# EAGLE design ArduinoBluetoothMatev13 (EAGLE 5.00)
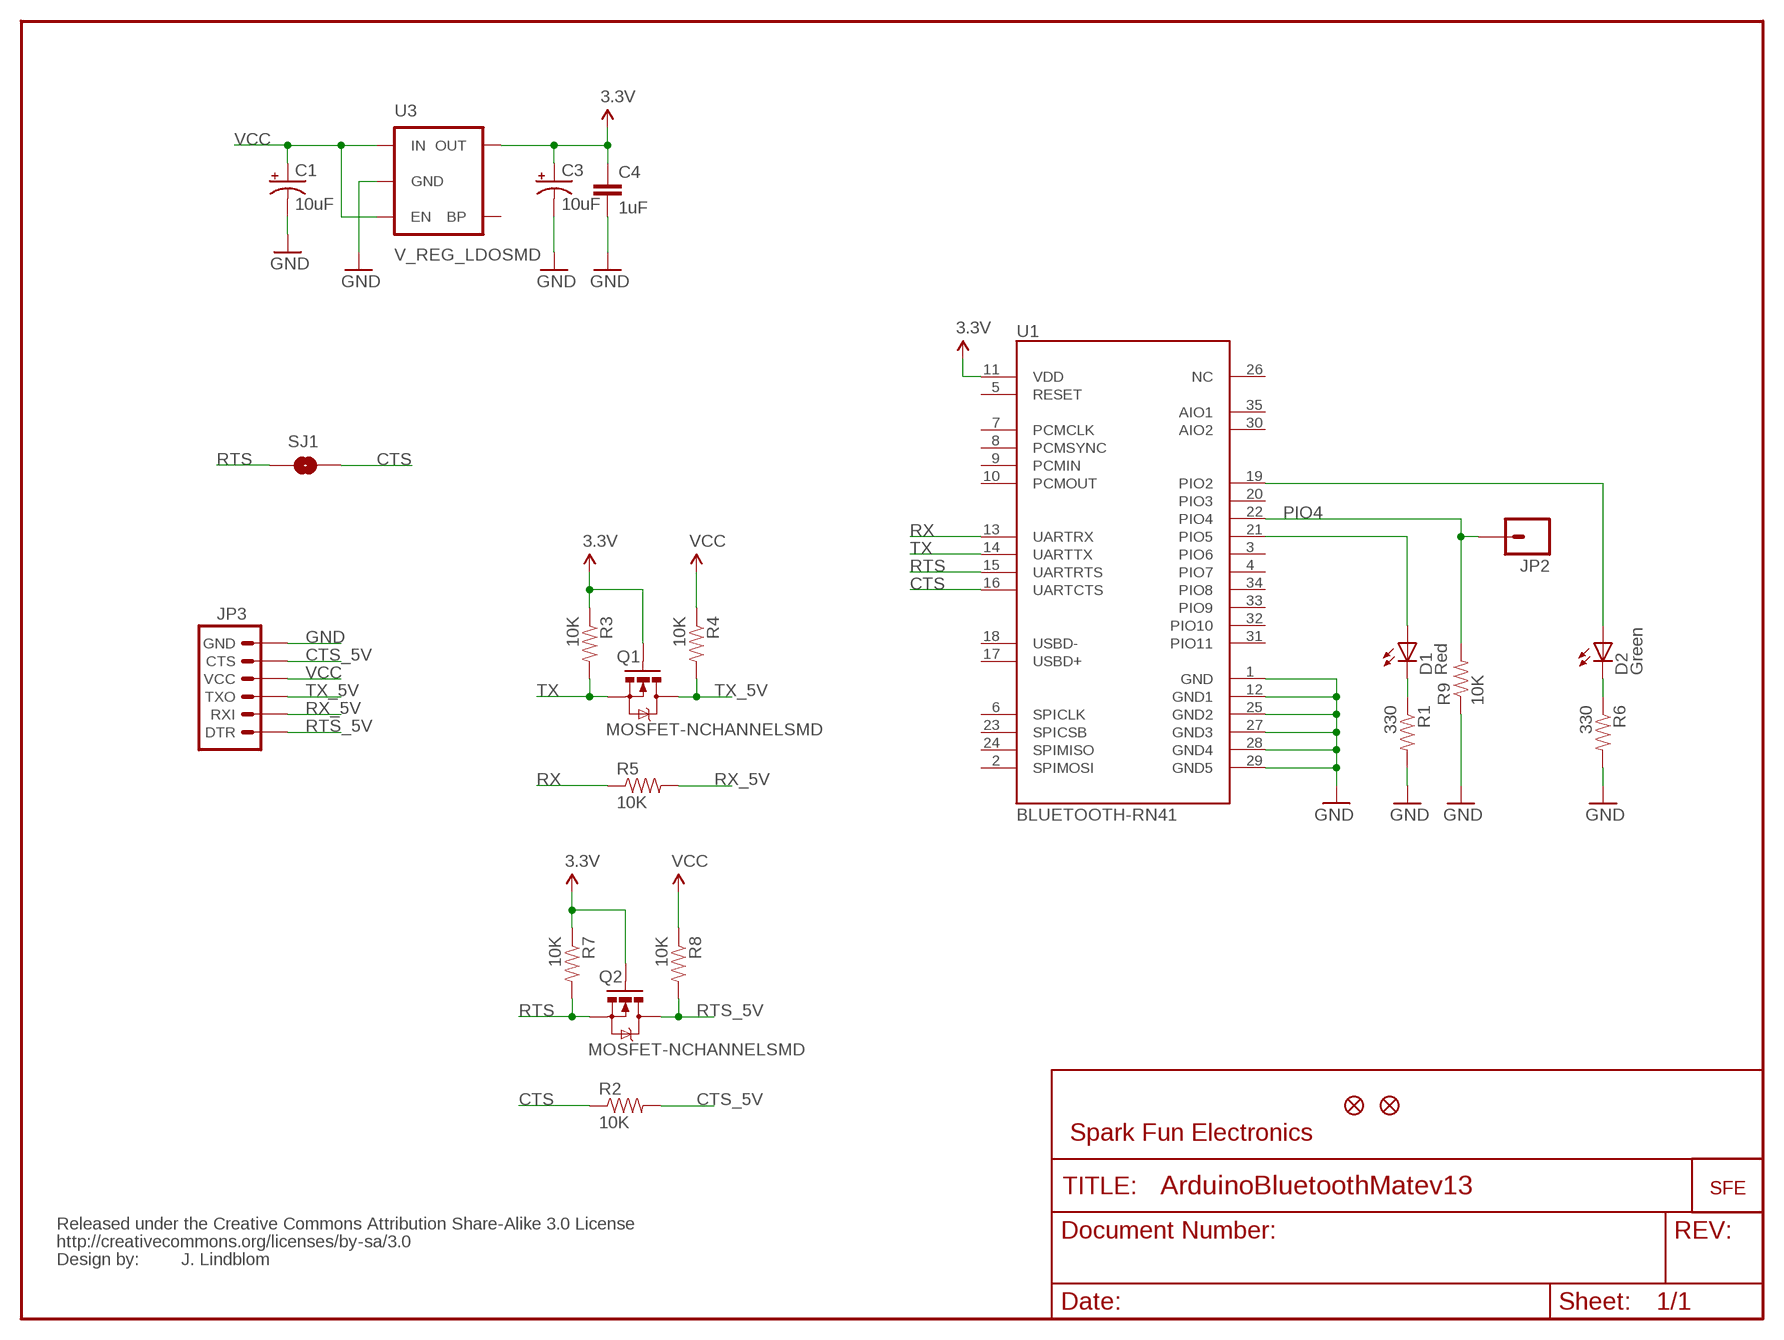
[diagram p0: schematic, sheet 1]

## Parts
C1  10uF  CAP_POL1206  [EIA3216]
C3  10uF  CAP_POL1206  [EIA3216]
C4  1uF  CAP0402-CAP  [0402-CAP]
D1  Red  LED0603  [LED-0603]
D2  Green  LED0603  [LED-0603]
JP1  FIDUCIAL1X2  [FIDUCIAL-1X2]
JP2  M01SMDNS  [1X01NS]
JP3  ARDUINO_SERIAL_PROGRAMPTH  [1X06]
JP4  FIDUCIAL1X2  [FIDUCIAL-1X2]
Q1  MOSFET-NCHANNELSMD  [SOT23-3]
Q2  MOSFET-NCHANNELSMD  [SOT23-3]
R1  330  RESISTOR0402-RES  [0402-RES]
R2  10K  RESISTOR0402-RES  [0402-RES]
R3  10K  RESISTOR0402-RES  [0402-RES]
R4  10K  RESISTOR0402-RES  [0402-RES]
R5  10K  RESISTOR0402-RES  [0402-RES]
R6  330  RESISTOR0402-RES  [0402-RES]
R7  10K  RESISTOR0402-RES  [0402-RES]
R8  10K  RESISTOR0402-RES  [0402-RES]
R9  10K  RESISTOR0402-RES  [0402-RES]
SJ1  SOLDERJUMPERNO  [SJ_2S-NO]
U1  BLUETOOTH-RN41  BLUETOOTH-RN41"  [RN41]
U3  V_REG_LDOSMD  [SOT23-5]
U$1  LOGO-SFENEW  [SFE-NEW-WEBLOGO]
U$2  CREATIVE_COMMONS  [CREATIVE_COMMONS]

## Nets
3.3V: C3.A(+) C4.1 Q1.1(G) Q2.1(G) R3.1 R7.1 U1.11(VDD) U3.5(OUT)
CTS: R2.1 SJ1.2 U1.16(UARTCTS)
CTS_5V: JP3.5(CTS) R2.2
D1: D1.C R1.1
D2: D2.C R6.1
GND: C1.C(-) C3.C(-) C4.2 JP3.6(GND) R1.2 R6.2 R9.1 U1.1(GND) U1.12(GND1) U1.25(GND2) U1.27(GND3) U1.28(GND4) U1.29(GND5) U3.2(GND)
N$1: D1.A U1.21(PIO5)
N$2: D2.A U1.19(PIO2)
PIO4: JP2.1 R9.2 U1.22(PIO4)
RTS: Q2.2(S) R7.2 SJ1.1 U1.15(UARTRTS)
RTS_5V: JP3.1(DTR) Q2.3(D) R8.2
RX: R5.1 U1.13(UARTRX)
RX_5V: JP3.2(RXI) R5.2
TX: Q1.2(S) R3.2 U1.14(UARTTX)
TX_5V: JP3.3(TXO) Q1.3(D) R4.2
VCC: C1.A(+) JP3.4(VCC) R4.1 R8.1 U3.1(IN) U3.3(EN)
Unconnected: U1.2(SPIMOSI) U1.3(PIO6) U1.4(PIO7) U1.5(RESET) U1.6(SPICLK) U1.7(PCMCLK) U1.8(PCMSYNC) U1.9(PCMIN) U1.10(PCMOUT) U1.17(USBD+) U1.18(USBD-) U1.20(PIO3) U1.23(SPICSB) U1.24(SPIMISO) U1.26(NC) U1.30(AIO2) U1.31(PIO11) U1.32(PIO10) U1.33(PIO9) U1.34(PIO8) U1.35(AIO1) U3.4(BP)

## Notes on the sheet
- Spark Fun Electronics
- J. Lindblom

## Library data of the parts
C1 C3 = SparkFun:CAP_POL: Capacitor Polarized
C4 = SparkFun:CAP: Capacitor
D1 D2 = SparkFun:LED: LEDs
JP1 JP4 = SparkFun:FIDUCIAL: Fiducial Alignment Points
JP2 = SparkFun:M01: Header 1
JP3 = SparkFun:ARDUINO_SERIAL_PROGRAM
Q1 Q2 = SparkFun:MOSFET-NCHANNEL
R1-R9 = SparkFun:RESISTOR: Resistor
SJ1 = SparkFun:SOLDERJUMPER: Solder Jumper
U1 = ScratchPad:BLUETOOTH-RN41
U3 = SparkFun:V_REG_LDO: Voltage Regulator LDO Standard 150mA LDO voltage regulator in SOT-23 layout. Micrel part MIC5205. BP (by-pass) pin is used to lower output noise with 470pF cap.
U$1 = SparkFun:LOGO-SFE: Spark Fun Electronics PCB Logo
U$2 = SparkFun:CREATIVE_COMMONS

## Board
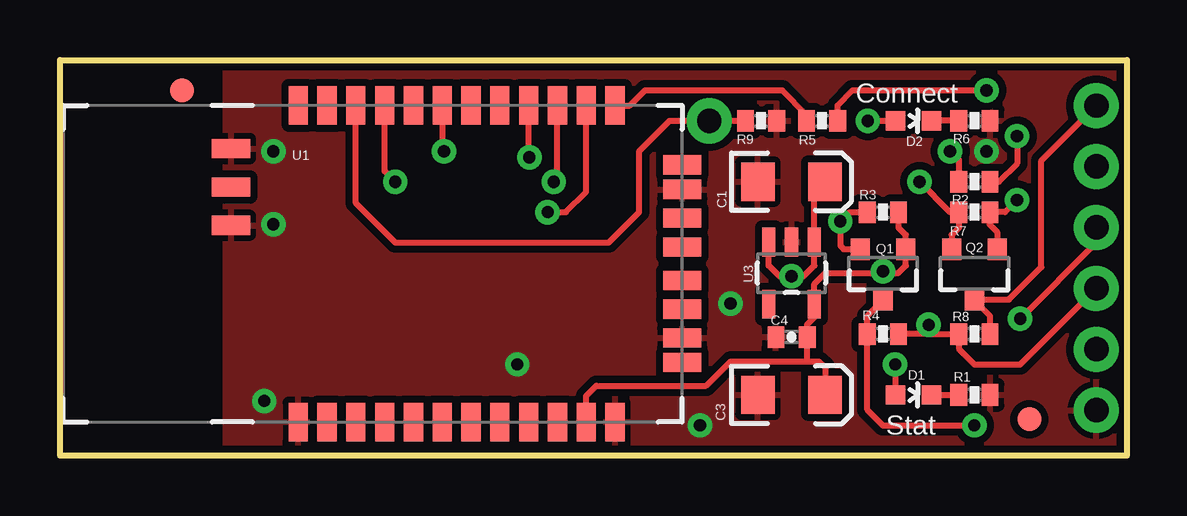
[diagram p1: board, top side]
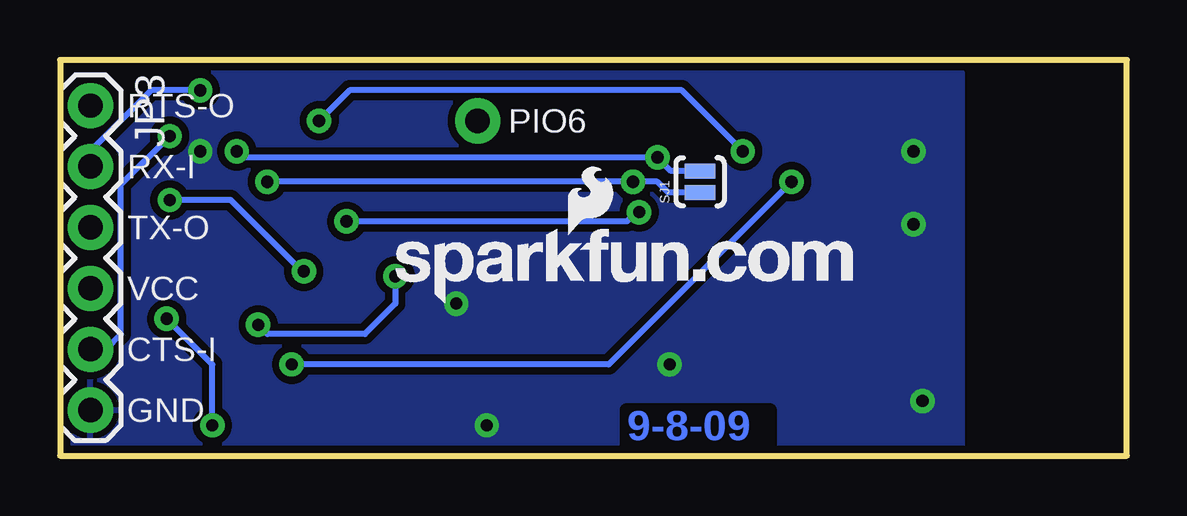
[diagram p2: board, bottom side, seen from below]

Size 44.45 x 16.51 mm. Coordinates in mm from the lower left corner, seen from the top.
Outline: 0,0 0,16.51 44.45,16.51 44.45,0 0,0
Copper layers (1*16): Top 0.035mm / dielectric 1.5mm / Bottom 0.035mm
Design rules "SparkFun": minimum track width 8mil, minimum drill 20mil, track to track 8mil, track to pad 8mil, pad to pad 8mil, via to via 8mil, smd to smd 8mil, copper to edge 9mil, drill to drill 8mil, minimum pad ring 12mil, minimum via ring 10mil, stop-mask expansion 4mil, vias tented up to drill 20mil, thermal gap 10mil

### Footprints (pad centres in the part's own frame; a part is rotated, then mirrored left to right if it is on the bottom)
EIA3216 = smd 1.4 x 1.6: A 1.4,0; C -1.4,0
0402-CAP = smd 0.7 x 0.9: 1 -0.65,0; 2 0.65,0
LED-0603 = smd 0.8 x 0.8: A 0,-0.75; C 0,0.75
FIDUCIAL-1X2 = smd 1 x 1: 1 0,0
1X01NS = drill 1.016 pad 1.88 round: 1 0,0
1X06 = drill 1.016 pad 1.88 round: 1 0,0; 2 2.54,0; 3 5.08,0; 4 7.62,0; 5 10.16,0; 6 12.7,0
SOT23-3 = smd 0.8 x 0.9: 1 -0.95,-1; 2 0.95,-1; 3 0,1.1
0402-RES = smd 0.7 x 0.9: 1 -0.65,0; 2 0.65,0
SJ_2S-NO = smd 0.635 x 1.27: 1 -0.45,0; 2 0.45,0
RN41 = smd 0.8 x 1.6: 1 -6.6,-6.6; 2 -5.4,-6.6; 3 -4.2,-6.6; 4 -3,-6.6; 5 -1.8,-6.6; 6 -0.6,-6.6; 7 0.6,-6.6; 8 1.8,-6.6; 9 3,-6.6; 10 4.2,-6.6; 11 5.4,-6.6; 12 6.6,-6.6; 13 6.6,6.6; 14 5.4,6.6; 15 4.2,6.6; 16 3,6.6; 17 1.8,6.6; 18 0.6,6.6; 19 -0.6,6.6; 20 -1.8,6.6; 21 -3,6.6; 22 -4.2,6.6; 23 -5.4,6.6; 24 -6.6,6.6 | smd 1.6 x 0.8: 25 -9.4,4.8; 26 -9.4,3.2; 27 -9.4,1.6; 28 9.4,3.1; 29 9.4,-3.1; 30 9.4,-4.122; 31 9.4,-1.9; 32 9.4,-0.7; 33 9.4,0.7; 34 9.4,1.9; 35 9.4,4.122
SOT23-5 = smd 0.55 x 1.2: 1 -0.95,-1.3; 2 0,-1.3; 3 0.95,-1.3; 4 0.95,1.3; 5 -0.95,1.3

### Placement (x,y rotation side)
C1  30.48,11.43 0 top
C3  30.48,2.54 0 top
C4  30.48,4.95 180 top
D1  35.56,2.54 270 top
D2  35.56,13.97 270 top
JP1  40.39,1.52 0 top
JP2  27.05,13.97 0 top
JP3  43.18,14.61 270 bottom
JP4  5.08,15.24 0 top
Q1  34.29,7.62 180 top
Q2  38.1,7.62 180 top
R1  38.1,2.54 0 top
R2  38.1,11.43 0 top
R3  34.29,10.16 180 top
R4  34.29,5.08 180 top
R5  31.75,13.97 0 top
R6  38.1,13.97 0 top
R7  38.1,10.16 180 top
R8  38.1,5.08 0 top
R9  29.21,13.97 180 top
SJ1  17.78,11.43 90 bottom
U1  16.53,8.01 0 top
U3  30.48,7.62 180 top
U$1  30.48,6.35 0 bottom
U$2  not placed on the board

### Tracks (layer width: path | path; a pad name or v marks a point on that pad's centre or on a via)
3.3V  (via drill 0.51)
  Top 0.254: Q2.1 39.05,9.34 38.73,9.65 38.75,9.67 R7.1 39.37,10.16 v39.88,10.67 | R3.1 34.94,9.51 35.24,9.21 Q1.1 35.24,7.93 34.92,7.62 34.29,7.62 | C3.A 31.88,3.68 31.62,3.94 31.11,3.94 | U1.11 21.93,2.5 22.35,2.92 26.92,2.92 27.94,3.94 31.11,3.94 | 34.29,7.62 31.88,7.62 31.43,7.17 U3.5 31.43,5.78 31.11,5.46 31.13,5.45 C4.1 31.13,3.95 31.11,3.94 | 34.29,7.62 v34.29,7.7
  Bottom 0.254: v39.88,10.67 37.34,10.67 34.29,7.62 v34.29,7.7
CTS  (via drill 0.51)
  Top 0.254: U1.16 19.53,12.48 v19.56,12.45 | R2.1 37.45,12.33 v37.08,12.7
  Bottom 0.254: SJ1.2 18.99,11.88 v19.56,12.45 36.83,12.45 v37.08,12.7
CTS_5V  (via drill 0.51)
  Top 0.254: R2.2 39.12,11.43 39.88,12.19 v39.88,13.34
  Bottom 0.254: JP3.5 42.55,4.45 41.91,5.08 41.91,11.3 v39.88,13.34
D1
  Top 0.254: 37.47,2.54 R1.1 D1.C
D2
  Top 0.254: 37.47,13.97 R6.1 D2.C
GND  (via drill 0.51)
  other vias: 27.94,6.35 26.67,1.27 38.61,12.7 8.89,12.7 8.89,9.65 8.51,2.29 19.05,3.81
  pour Bottom (isolate 0.305): 6.86,0 44.4,0 44.4,16 6.86,16
  pour Top (isolate 0.305): 6.86,0 44.4,0 44.4,16 6.86,16
N$1  (via drill 0.51)
  Top 0.254: D1.A 34.81,3.29 v34.8,3.81 | U1.21 13.53,11.87 v13.97,11.43
  Bottom 0.254: v34.8,3.81 21.59,3.81 v13.97,11.43
N$2  (via drill 0.51)
  Top 0.254: U1.19 15.93,12.78 v16,12.7 | v33.66,13.97 D2.A
  Bottom 0.254: v16,12.7 18.54,15.24 32.38,15.24 v33.66,13.97
PIO4
  Top 0.254: U1.22 12.33,10.53 13.97,8.89 22.86,8.89 24.13,10.16 24.13,12.7 25.4,13.97 JP2.1 R9.2
RTS  (via drill 0.51)
  Top 0.254: Q2.2 37.15,9.21 37.45,9.51 R7.2 37.45,10.18 37.07,10.18 v35.81,11.43 | U1.15 20.73,11.58 v20.57,11.43
  Bottom 0.254: SJ1.1 19.11,10.98 19.56,11.43 v20.57,11.43 v35.81,11.43
RTS_5V
  Top 0.254: R8.2 38.75,5.83 38.1,6.48 Q2.3 39.54,6.52 40.89,7.87 40.89,12.32 JP3.1
RX
  Top 0.254: R5.1 31.1,14.24 30.1,15.24 24.38,15.24 23.75,14.61 U1.13
RX_5V  (via drill 0.51)
  Top 0.254: R5.2 32.4,14.62 33.02,15.24 v38.61,15.24
  Bottom 0.254: JP3.2 43.18,12.7 40.64,15.24 v38.61,15.24
TX  (via drill 0.51)
  Top 0.254: R3.2 32.89,10.16 v32.51,9.78 32.51,8.76 32.66,8.62 Q1.2 | U1.14 21.93,11 21.08,10.16 v20.32,10.16
  Bottom 0.254: v20.32,10.16 20.45,10.16 20.83,9.78 v32.51,9.78
TX_5V  (via drill 0.51)
  Top 0.254: 34.29,6.6 Q1.3 34.29,6.48 33.64,5.83 R4.2 33.64,1.92 34.29,1.27 v38.1,1.27 | JP3.3 43.18,8.89 v40.01,5.71
  Bottom 0.254: v40.01,5.71 38.1,3.81 v38.1,1.27
VCC  (via drill 0.51)
  Top 0.254: U3.3 29.53,7.93 29.97,7.49 v30.48,7.49 30.99,7.49 31.43,7.93 U3.1 31.43,10.98 C1.A | R8.1 37.47,5.08 | 34.92,5.08 R4.1 36.2,5.08 | 36.2,5.08 R8.1 | v36.2,5.46 36.2,5.08 | R8.1 37.45,4.46 38.1,3.81 40.01,3.81 JP3.4
  Bottom 0.254: v30.48,7.49 30.48,6.35 31.75,5.08 35.81,5.08 v36.2,5.46

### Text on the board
Bottom: 9-8-09
tPlace: Connect | Stat
bPlace: RTS-O | PIO6 | RX-I | TX-O | VCC | CTS-I | GND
